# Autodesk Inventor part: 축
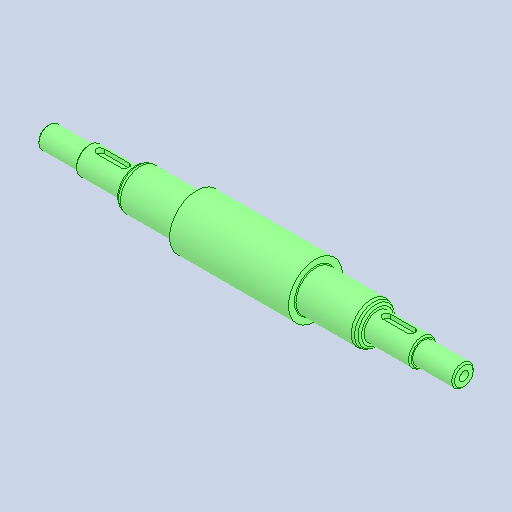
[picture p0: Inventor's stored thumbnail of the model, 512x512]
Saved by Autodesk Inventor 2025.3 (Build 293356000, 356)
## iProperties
Created: 2025-10
Part Number: 축
Material: 강철, 탄소
Document SubType Name: Modeling
Designer: USER
Density: 7.85 g/cm^3
Appearance: 기본값
Author: jhkim
Sending System: Autodesk Inventor 2026
Preprocessor: ST-DEVELOPER v20.1
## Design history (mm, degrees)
feature "솔리드1"
node "솔리드2"
